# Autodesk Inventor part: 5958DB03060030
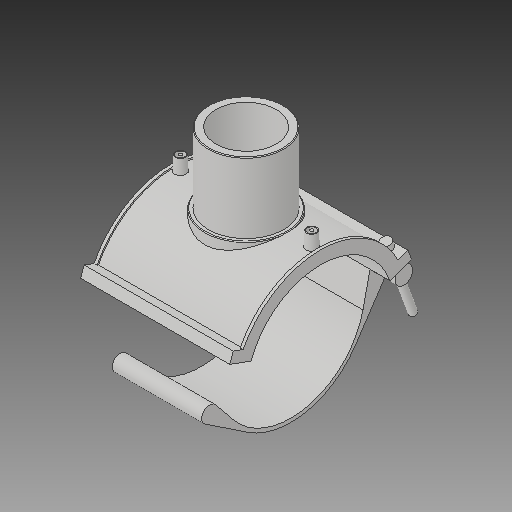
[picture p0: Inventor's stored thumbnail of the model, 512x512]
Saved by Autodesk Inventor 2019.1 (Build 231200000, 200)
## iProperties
Created: 2017-07
Part Number: 5958DB03060030
Material: Generic
Description: PLASSON BRANCH SADDLE 6''DIPS x 3''IPS
Document SubType Name: Modeling
Designer: KIM
Mass: 764.267 g
Surface Area: 1930.38 cm^2
Volume: 764.267 cm^3
Density: 1 g/cm^3
Appearance: Default
Author: KIM
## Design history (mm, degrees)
derived "5958D (2).ipt"
feature "Solid6::5958D (2).ipt"
tag "TaggingFeature1"
body "Solid1"
other parameters: "d244" = 174.5, "d245" = 13.462, "d248" = 176.784, "d249" = 88.392, "d252" = 87.25, "d254" = 13.462, "d256" = 530.352, "d257" = 21.8125, "d258" = 265.176, "d259" = 0.5, "d260" = 176.022, "d261" = 0, "d287" = 101.25048, "d288" = 97.57, "d290" = 0, "d291" = 184.278, "d292" = 88.7, "d294" = 0, "d309" = 117.25, "d310" = 12, "d311" = 12, "d315" = 3 deg, "d316" = 4, "d318" = 4, "d320" = 14, "d321" = 0, "d331" = 0.887, "d332" = 70.96, "d334" = 0, "d337" = 0.887, "d340" = 10.56132, "d341" = 10.56132, "d342" = 20 deg, "d343" = 20 deg, "d344" = 707.136, "d345" = 174.5, "d347" = 0, "d352" = 26.924, "d353" = 12.215, "d355" = 0, "d356" = 20 deg, "d357" = 26.175, "d358" = 174.5, "d359" = 183.225, "d360" = 20.94, "d361" = 10 deg, "d362" = 5.99059, "d363" = 34.9, "d366" = 95.975, "d367" = 6.25983, "d368" = 105.6132, "d369" = 0, "d370" = 158.4198, "d371" = 0, "d372" = 132.0165, "d374" = 8.725, "d375" = 12.215, "d376" = 8.725, "d377" = 12.215, "d378" = 87.25, "d379" = 0, "d380" = 7.329, "d381" = 0, "d383" = 107.443, "d384" = 17.6022, "d385" = 1.745, "d386" = 3.52044, "d387" = 0, "d389" = 360 deg, "d_" = 174.5, "d1" = 88.7, "B_" = 176.784, "H_" = 97.028, "H1" = 83.566, "L" = 176.022, "t" = 6
